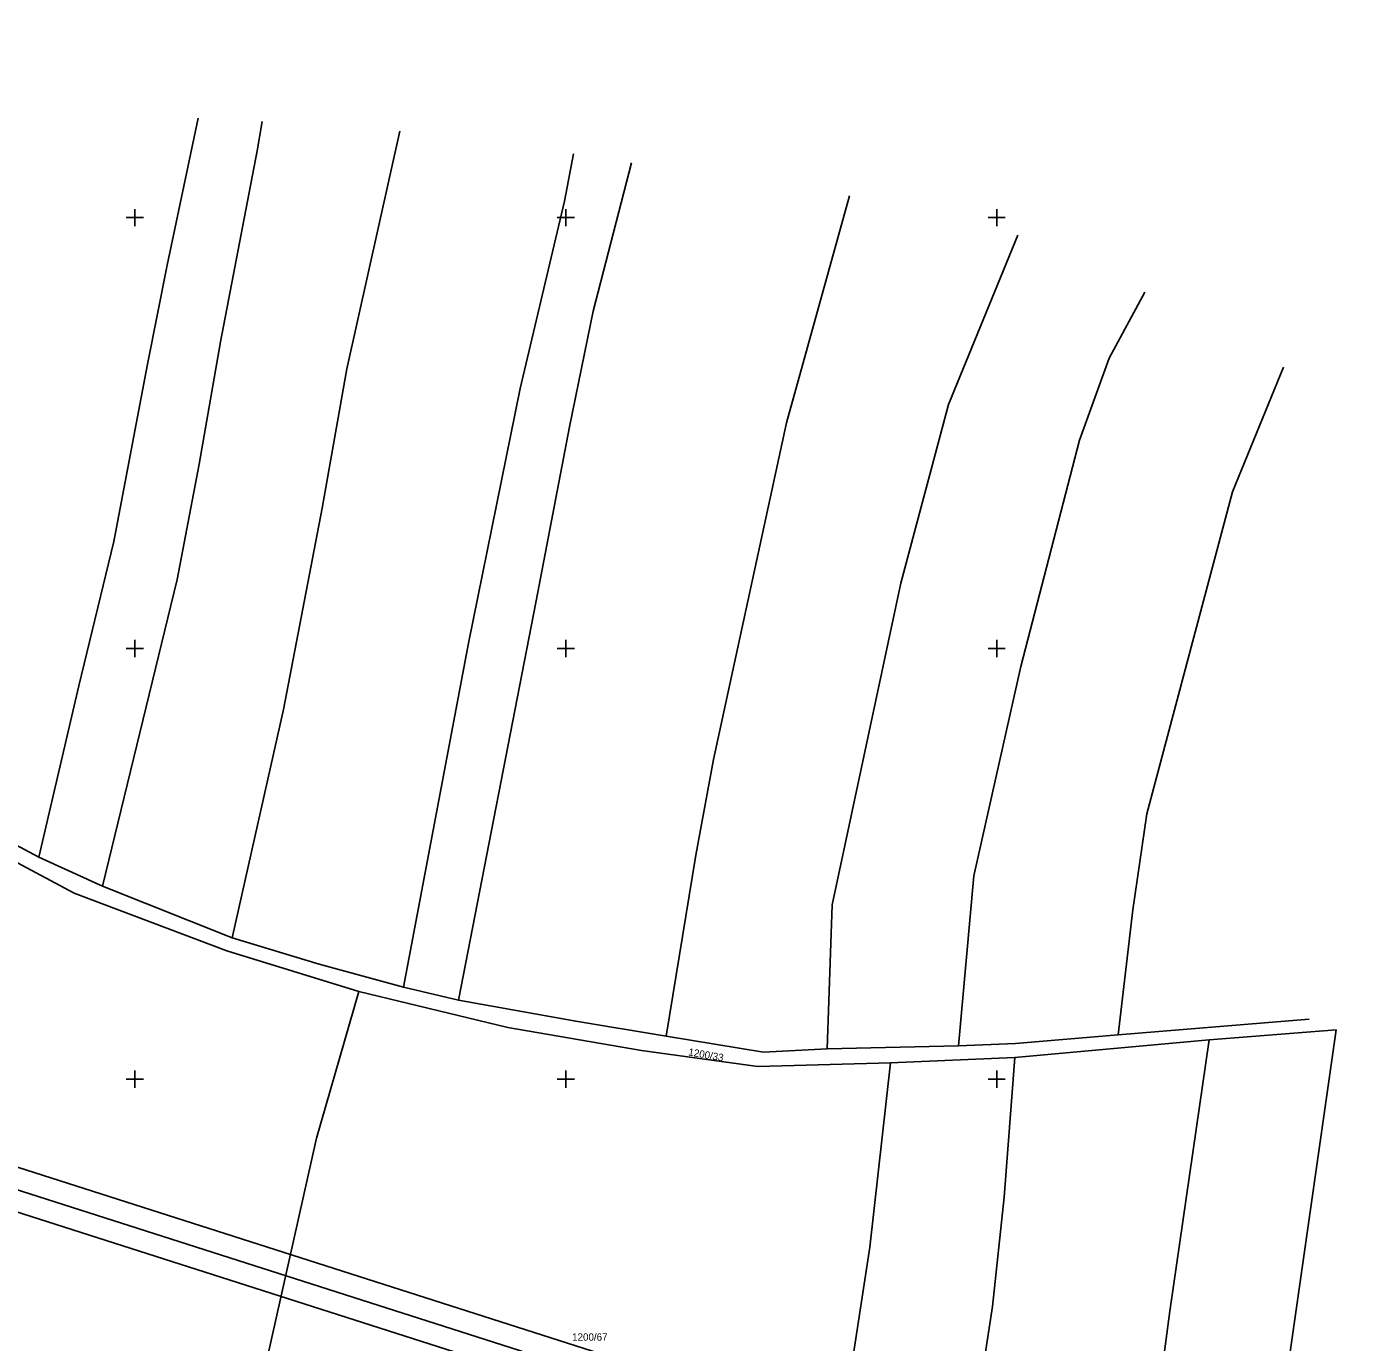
# Model space of a CAD drawing. Extents: x -779302 to -774398, y -1144902 to -1142831.
# Drawn here: x -776925.1 to -776612.7, y -1143761 to -1143455.7 of the extents above; entities that cross this region are included whole.
import ezdxf

# ---------------------------------------------------------------- set-up
doc = ezdxf.new("R2010")
doc.units = 0
for name, color, linetype in [('hektosit - Vrstva 5', 7, 'Continuous'), ('Hranice parcel', 7, 'Continuous'), ('Parcelní čísla', 7, 'Continuous'), ('Vrstva 1', 7, 'Continuous')]:
    doc.layers.add(name, color=color, linetype=linetype)

msp = doc.modelspace()

# ---------------------------------------------------------------- linework, layer by layer
at = {"layer": 'hektosit - Vrstva 5'}
for p, q in [((-776902, -1143500), (-776898, -1143500)), ((-776900, -1143498), (-776900, -1143502)), ((-776802, -1143500), (-776798, -1143500)), ((-776800, -1143498), (-776800, -1143502)), ((-776702, -1143500), (-776698, -1143500)), ((-776700, -1143498), (-776700, -1143502)), ((-776902, -1143600), (-776898, -1143600)), ((-776900, -1143598), (-776900, -1143602)), ((-776802, -1143600), (-776798, -1143600)), ((-776800, -1143598), (-776800, -1143602)), ((-776702, -1143600), (-776698, -1143600)), ((-776700, -1143598), (-776700, -1143602)), ((-776902, -1143700), (-776898, -1143700)), ((-776900, -1143698), (-776900, -1143702)), ((-776802, -1143700), (-776798, -1143700)), ((-776800, -1143698), (-776800, -1143702)), ((-776702, -1143700), (-776698, -1143700)), ((-776700, -1143698), (-776700, -1143702))]:
    msp.add_line(p, q, dxfattribs=at)
at = {"layer": 'Hranice parcel'}
for p, q in [((-776907.53, -1143655.21), (-776922.26, -1143648.45)), ((-776877.4, -1143667.15), (-776907.53, -1143655.21)), ((-776824.91, -1143681.69), (-776837.67, -1143678.67)), ((-776627.48, -1143686.05), (-776671.82, -1143689.69)), ((-776695.8, -1143695), (-776650.69, -1143690.83)), ((-776650.69, -1143690.83), (-776621.25, -1143688.51)), ((-776708.85, -1143692.25), (-776739.36, -1143692.99)), ((-776724.63, -1143696.21), (-776695.8, -1143695))]:
    msp.add_line(p, q, dxfattribs=at)
for points in [[(-776922.26, -1143648.45), (-776912.97, -1143608.66), (-776904.9, -1143575.18), (-776897.06, -1143534.03), (-776892.52, -1143511.06), (-776885.32, -1143476.92)], [(-776907.53, -1143655.21), (-776890.21, -1143583.97), (-776885.05, -1143557.23), (-776880.16, -1143528.84), (-776871.61, -1143484.5), (-776870.45, -1143477.64)], [(-776877.4, -1143667.15), (-776865.51, -1143614.2), (-776856.5, -1143567.42), (-776850.8, -1143535.07), (-776838.54, -1143479.92)], [(-776837.67, -1143678.67), (-776822.59, -1143598.77), (-776810.56, -1143539.68), (-776800.3, -1143496.2), (-776798.2, -1143485.2)], [(-776824.91, -1143681.69), (-776806.89, -1143588.95), (-776799.17, -1143548.56), (-776793.63, -1143521.67), (-776784.78, -1143487.25)], [(-776776.74, -1143690.04), (-776769.84, -1143648.01), (-776765.71, -1143625.8), (-776748.8, -1143547.65), (-776734.19, -1143494.92)], [(-776739.36, -1143692.99), (-776738.19, -1143659.54), (-776722.23, -1143584.84), (-776711.2, -1143543.35), (-776695.1, -1143504.06)], [(-776708.85, -1143692.25), (-776705.27, -1143652.79), (-776694.4, -1143604.19), (-776680.75, -1143551.69), (-776673.89, -1143532.63), (-776665.62, -1143517.31)], [(-776671.82, -1143689.69), (-776668.44, -1143660.72), (-776665.18, -1143638.43), (-776645.25, -1143563.67), (-776633.47, -1143534.74)], [(-776848.03, -1143679.63), (-776878.65, -1143670.22), (-776914.12, -1143656.82), (-776952.75, -1143636.13), (-776967.87, -1143627.57), (-776994.01, -1143610.04)], [(-776922.26, -1143648.45), (-776952.47, -1143632.4), (-776959.28, -1143628.68), (-776966.54, -1143624.26), (-776979.62, -1143616.01)], [(-776837.67, -1143678.67), (-776857.25, -1143673.27), (-776877.4, -1143667.15)], [(-776871.42, -1143774.12), (-776857.89, -1143713.73), (-776848.03, -1143679.63)], [(-776848.03, -1143679.63), (-776813.44, -1143688.04), (-776782.42, -1143693.37), (-776755.46, -1143697.07), (-776724.63, -1143696.21)], [(-776776.74, -1143690.04), (-776797.7, -1143686.57), (-776824.91, -1143681.69)], [(-776739.36, -1143692.99), (-776754.15, -1143693.73), (-776776.74, -1143690.04)], [(-776671.82, -1143689.69), (-776695.6, -1143691.74), (-776708.85, -1143692.25)], [(-776669.89, -1143829.58), (-776659.83, -1143753.85), (-776650.69, -1143690.83)], [(-776640.68, -1143832.31), (-776633.12, -1143771.99), (-776621.25, -1143688.51)], [(-776742.31, -1143822.8), (-776729.45, -1143739.01), (-776724.63, -1143696.21)], [(-776712.16, -1143825.63), (-776701, -1143752.75), (-776698.23, -1143727.38), (-776695.8, -1143695)]]:
    msp.add_lwpolyline(points, dxfattribs=at)
at = {"layer": 'Vrstva 1'}
for points in [[(-776606.88, -1143822.95), (-777806.9, -1143438.86), (-777897.43, -1143721.71), (-776697.42, -1144105.81)], [(-776700.65, -1144099.52), (-777891.15, -1143718.47), (-777803.66, -1143445.14), (-776613.17, -1143826.19)], [(-776619.45, -1143829.42), (-777605.19, -1143513.91), (-777689.63, -1143777.73), (-776703.89, -1144093.24)], [(-776703.89, -1144093.24), (-777689.63, -1143777.73), (-777605.19, -1143513.91), (-776619.45, -1143829.42)]]:
    msp.add_lwpolyline(points, close=True, dxfattribs=at)

# ---------------------------------------------------------------- texts
at = {"layer": 'Parcelní čísla'}
msp.add_text('1200/33', height=1.7, rotation=350, dxfattribs=at).set_placement((-776771.65, -1143694.46))
msp.add_text('1200/67', height=1.7, dxfattribs=at).set_placement((-776798.53, -1143760.71))

doc.saveas('drawing.dxf')
